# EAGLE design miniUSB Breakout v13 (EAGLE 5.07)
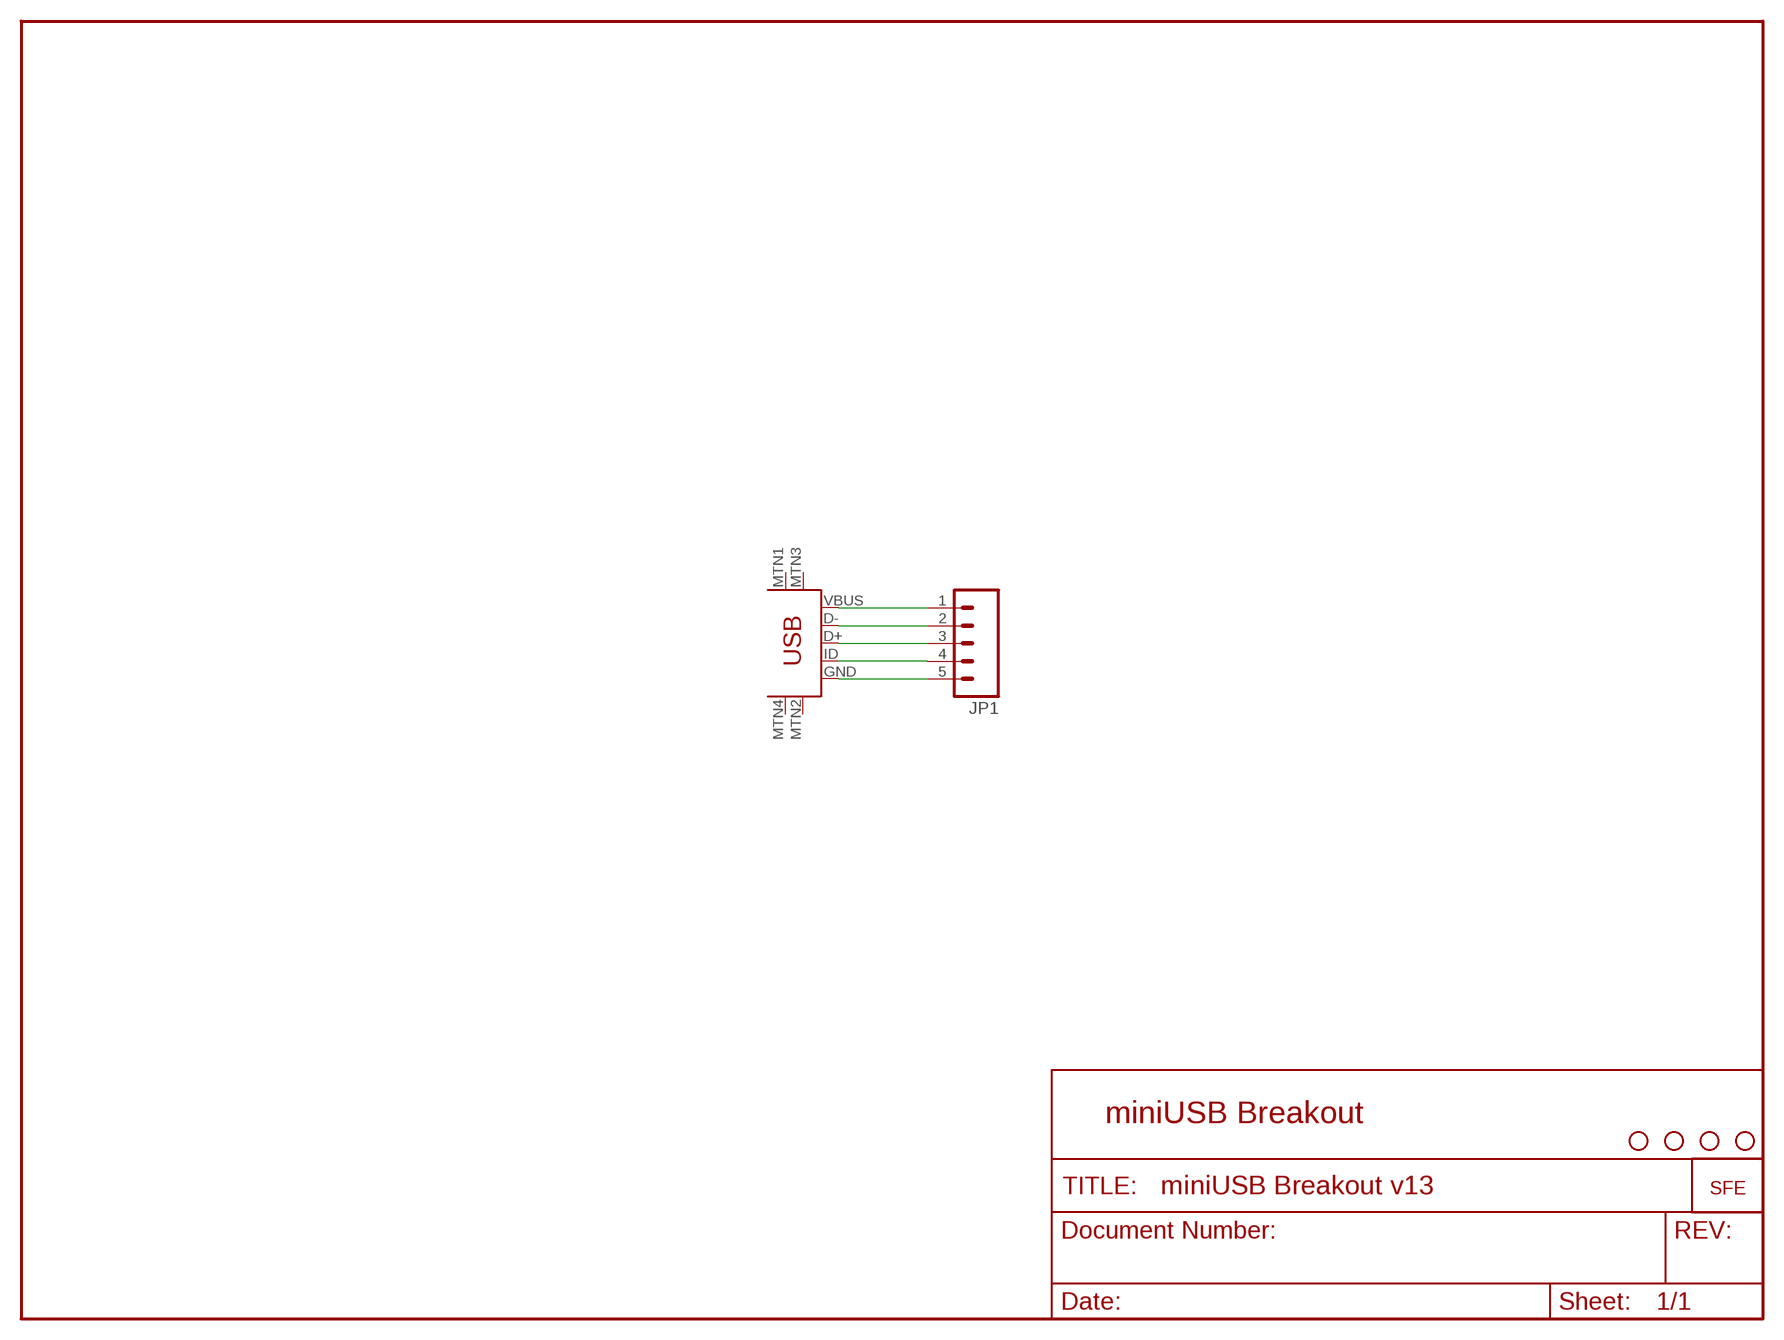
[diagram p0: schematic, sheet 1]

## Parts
JP1  M05PTH  [1X05]
U$1  USB-MINIB-5PIN  [USB-MINIB]
U$2  STAND-OFF  [STAND-OFF]
U$3  STAND-OFF  [STAND-OFF]
U$4  STAND-OFF  [STAND-OFF]
U$5  STAND-OFF  [STAND-OFF]
U$6  LOGO-SFENEW  [SFE-NEW-WEBLOGO]

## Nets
GND: JP1.5 U$1.GND
N$1: JP1.2 U$1.D-
N$2: JP1.1 U$1.VBUS
N$3: JP1.3 U$1.D+
N$5: JP1.4 U$1.ID
Unconnected: U$1.MTN1(MTN2) U$1.MTN2(MTN3) U$1.MTN3(MTN1) U$1.MTN4

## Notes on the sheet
- miniUSB Breakout

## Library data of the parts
JP1 = SparkFun:M05: Header 5 Standard 5-pin 0.1" header. Use with straight break away headers (SKU : PRT-00116), right angle break away headers (PRT-00553), swiss pins (PRT-00743), machine pins (PRT-00117), and female headers (PRT-00115). Molex polarized connector foot print use with SKU : PRT-08230 with associated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
U$1 = SparkFun:USB-MINIB
U$2-U$5 = SparkFun:STAND-OFF: Stand Off
U$6 = SparkFun:LOGO-SFE: Spark Fun Electronics PCB Logo

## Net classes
0 default: width 0.203 mm
1 power: width 0.305 mm

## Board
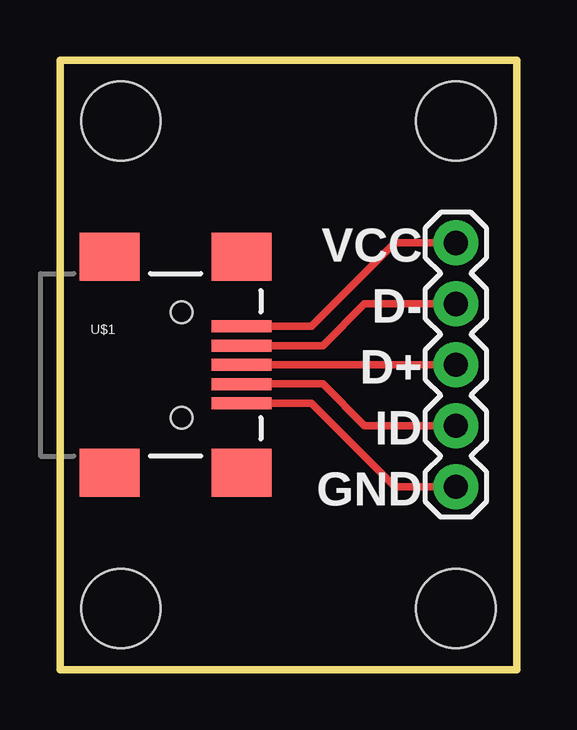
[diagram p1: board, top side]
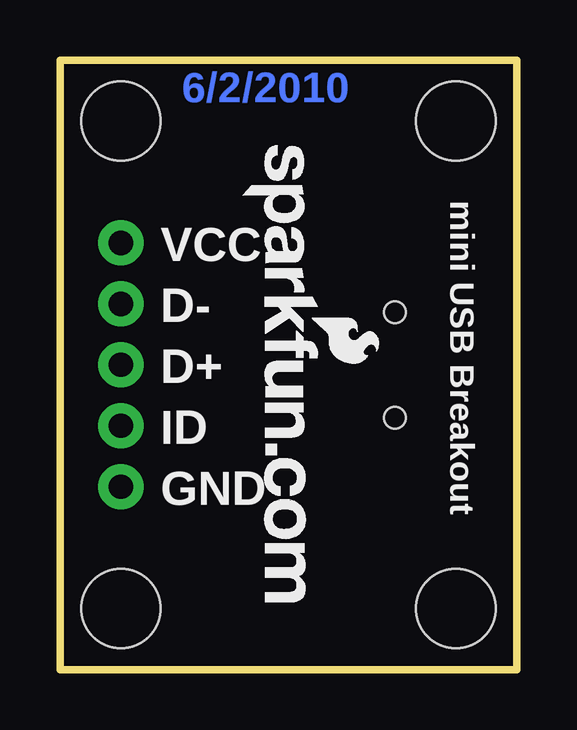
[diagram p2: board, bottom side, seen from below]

Size 19.05 x 25.4 mm. Coordinates in mm from the lower left corner, seen from the top.
Outline: 0,25.4 19.05,25.4 19.05,0 0,0 0,25.4
Copper layers (1*16): Top 0.035mm / dielectric 1.5mm / Bottom 0.035mm
Design rules "SparkFun": minimum track width 8mil, minimum drill 20mil, track to track 8mil, track to pad 8mil, pad to pad 8mil, via to via 8mil, smd to smd 8mil, copper to edge 10mil, drill to drill 8mil, minimum pad ring 12mil, minimum via ring 10mil, stop-mask expansion 4mil, vias tented up to drill 20mil, thermal gap 10mil

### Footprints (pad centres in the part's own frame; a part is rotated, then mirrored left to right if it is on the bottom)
1X05 = drill 1.016 pad 1.88 round: 1 0,0; 2 2.54,0; 3 5.08,0; 4 7.62,0; 5 10.16,0
USB-MINIB = smd 2.5 x 0.5: D+ 2.5,0; D- 2.5,0.8; GND 2.5,-1.6; ID 2.5,-0.8; VBUS 2.5,1.6 | smd 2.5 x 2: MTN1 -3,4.5; MTN2 2.5,4.5; MTN3 -3,-4.5; MTN4 2.5,-4.5 | hole 0.9: 0,2.2; 0,-2.2
STAND-OFF = hole 3.302: 0,0

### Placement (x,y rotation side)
JP1  16.51,17.78 270 top
U$1  5.08,12.7 0 top
U$2  16.51,2.54 0 top
U$3  2.54,2.54 0 top
U$4  2.54,22.86 0 top
U$5  16.51,22.86 0 top
U$6  11.43,21.84 270 bottom

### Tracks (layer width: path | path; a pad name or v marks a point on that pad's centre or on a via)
GND
  Top 0.305: U$1.GND 10.49,11.1 13.97,7.62 JP1.5
N$1
  Top 0.305: U$1.D- 10.96,13.5 12.7,15.24 JP1.2
N$2
  Top 0.305: U$1.VBUS 10.49,14.3 13.97,17.78 JP1.1
N$3
  Top 0.305: U$1.D+ JP1.3
N$5
  Top 0.305: U$1.ID 10.96,11.9 12.7,10.16 JP1.4

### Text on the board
Bottom: 6/2/2010
tPlace: VCC | D- | D+ | ID | GND
bPlace: mini USB Breakout | VCC | D- | D+ | ID | GND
